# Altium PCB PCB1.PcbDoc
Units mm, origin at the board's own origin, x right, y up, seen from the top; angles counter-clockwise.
Board outline 99.99 x 40 mm, 2 copper layers (Top Layer, Bottom Layer); 5 components, 6 nets, 38 pads, 0 vias.
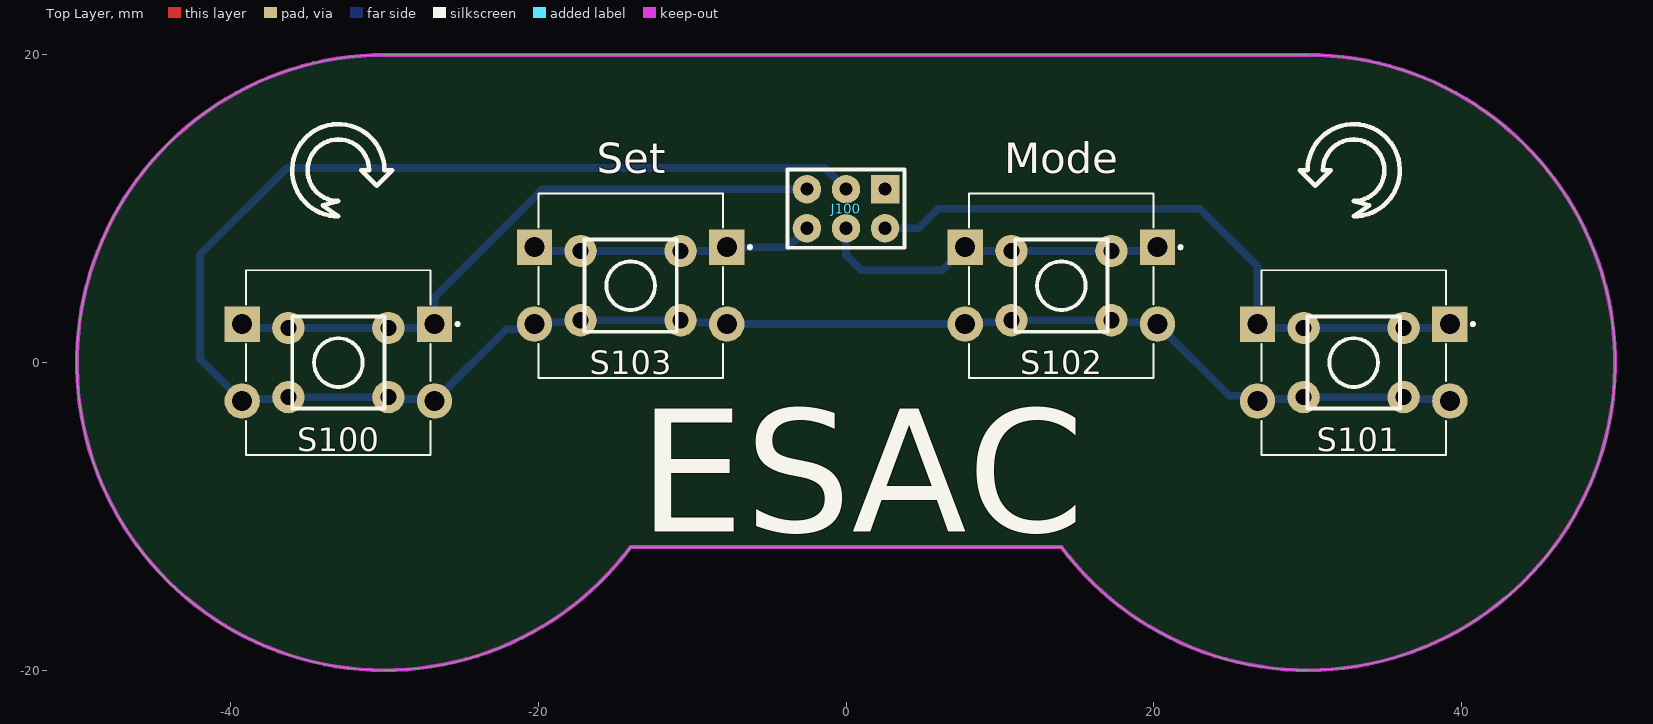
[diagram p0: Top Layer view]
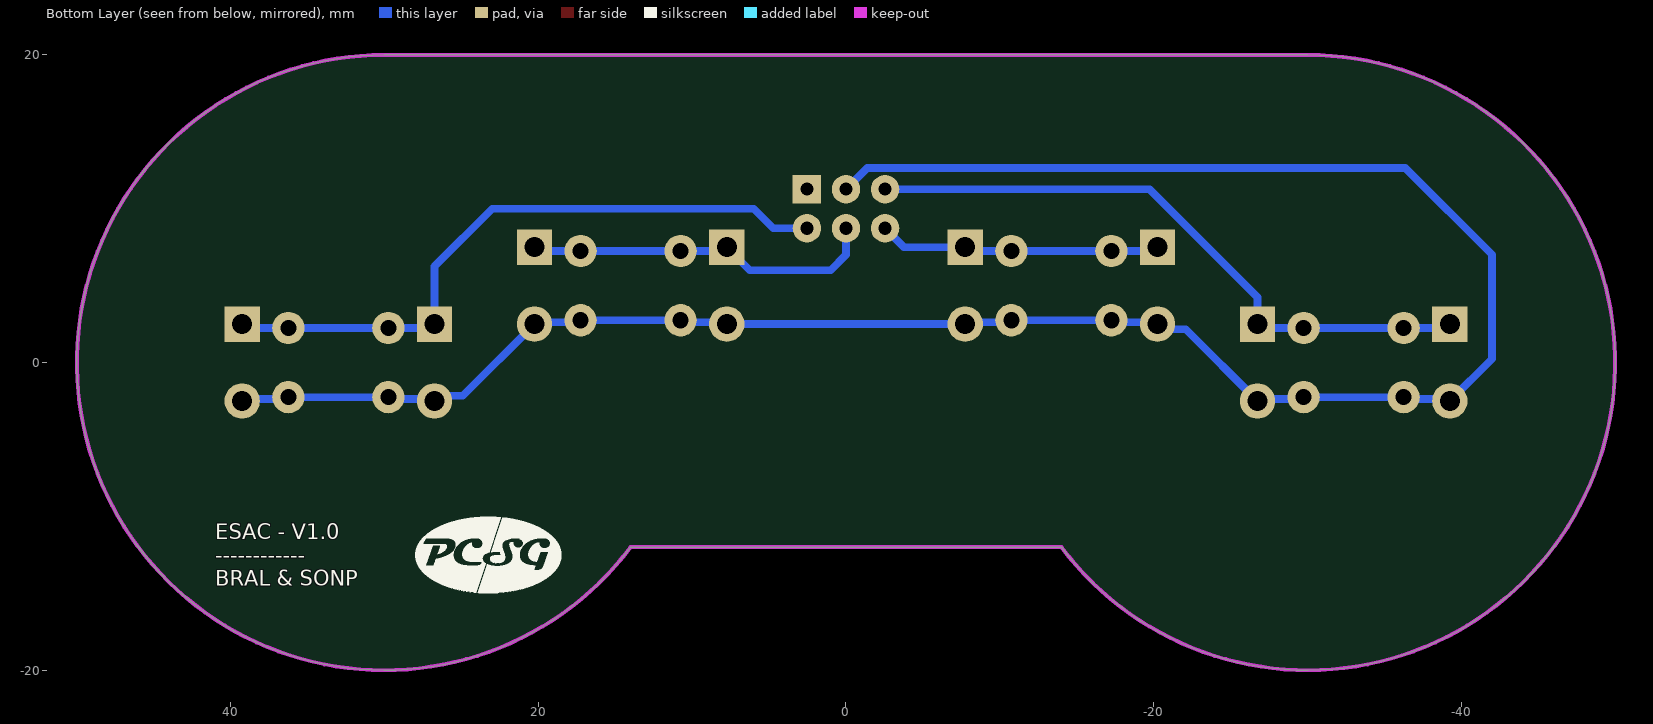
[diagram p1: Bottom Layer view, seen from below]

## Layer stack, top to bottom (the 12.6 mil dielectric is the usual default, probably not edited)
Top Solder: solder mask 0.0102, Solder Resist, Dk 3.5
Top Layer: signal copper 0.0356
Dielectric 1: dielectric 0.32, FR-4, Dk 4.8
Bottom Layer: signal copper 0.0356
Bottom Solder: solder mask 0.0102, Solder Resist, Dk 3.5

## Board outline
-14,-12 cw(c-30,0) -29.999,20 30,20 cw(c30,0) 14,-12

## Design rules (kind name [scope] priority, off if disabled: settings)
Clearance [All] p1: gap=0.5 ignorepadtopadclearanceinfootprint=FALSE except(0.2: Arc-Arc Arc-Track Arc-SMDPad Arc-THPad Arc-Via Arc-Text Arc-Hole Track-Track Track-SMDPad Track-THPad Track-Via Track-Text Track-Hole SMDPad-SMDPad SMDPad-THPad SMDPad-Via SMDPad-Text SMDPad-Hole THPad-THPad THPad-Via THPad-Text THPad-Hole Via-Via Via-Text Via-Hole Text-Text Text-Hole)
HoleSize [All] p1: absolutevalues=TRUE maxlimit=4 minlimit=0.25 maxpercent=80.000 minpercent=20.000
MinimumAnnularRing [All] p1: minimumring=0.3
MinimumSolderMaskSliver [All] p1: minsoldermaskwidth=0
PolygonConnect [All] p1: connectstyle=Relief reliefconductorwidth=0.3 reliefentries=4 polygonreliefangle="90 Angle" airgapwidth=0.3
RoutingVias [All] p1: holewidth=0.6 width=1.2 viastyle="Through Hole" minholewidth=0.5 minwidth=1 maxholewidth=1 maxwidth=2
SilkToSilkClearance [All] p1: silktosilkclearance=0
SilkToSolderMaskClearance [IsPad] p1: minsilkscreentomaskgap=0 clearancetoexposedcopper=TRUE
SolderMaskExpansion [All] p1: expansion=0.102 istentingtop=FALSE
Width [All] p1: maxlimit=6 minlimit=0.2 preferedwidth=0.5
26 further rules are at their usual default settings.

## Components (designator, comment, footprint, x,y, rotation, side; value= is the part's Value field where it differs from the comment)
J100 "CON 2x3" J_2x3 0,10 r180 top
S100 "Taster4Kl." S_THT_TasterKomb. -33,0 r180 top
S101 "Taster4Kl." S_THT_TasterKomb. 33,0 r180 top
S102 "Taster4Kl." S_THT_TasterKomb. 14,5 r180 top
S103 "Taster4Kl." S_THT_TasterKomb. -14,5 r180 top

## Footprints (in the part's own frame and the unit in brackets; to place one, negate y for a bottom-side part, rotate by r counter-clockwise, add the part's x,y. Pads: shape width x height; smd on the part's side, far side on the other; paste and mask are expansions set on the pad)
J_2x3 [mm] "LB-2024-04-19"
  rect 1.85x1.85 hole 0.85 mask+0.102: 1(-2.54,-1.27)
  round 1.85 hole 0.85 mask+0.102: 2(-2.54,1.27) 3(0,-1.27) 4(0,1.27) 5(2.54,-1.27) 6(2.54,1.27)
  silkscreen extent -3.81,-2.54 3.81,2.54
S_THT_TasterKomb. [mm] "LB-2024-04-17"
  rect 2.3x2.3 hole 1.3: 1(-6.25,-2.5) 1(6.25,-2.5)
  round 2.1 hole 1.05: 1(-3.25,-2.25) 1(3.25,-2.25) 2(-3.25,2.25) 2(3.25,2.25)
  round 2.3 hole 1.3: 2(-6.25,2.5) 2(6.25,2.5)
  silkscreen extent -7.85,-6 6,6

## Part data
J100: library part "J_THT_IDC 2x3", "Stecker"
S100 S101 S102 S103: library part S_THT_Taster, "Taster"

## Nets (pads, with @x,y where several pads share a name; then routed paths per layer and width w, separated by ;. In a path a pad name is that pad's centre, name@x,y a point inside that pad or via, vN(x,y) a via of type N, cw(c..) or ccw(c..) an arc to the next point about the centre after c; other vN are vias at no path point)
+5V: J100.3 S100.2 S101.2 S102.2 S103.2 | length 139.4
  Top Layer w0.5: J100.3@-0.258,11.528 J100.3
  Bottom Layer w0.5: J100.3 -1.375,12.645 -36.355,12.645 -42,7 -42,0.25 -39.25,-2.5 -39.125,-2.375 -36.375,-2.375 -36.25,-2.25 -29.75,-2.25 -29.625,-2.375 -26.875,-2.375 -26.75,-2.5 -22.094,2.156 -20.594,2.156 -20.25,2.5 -20.125,2.625 -17.375,2.625 -17.25,2.75 -10.75,2.75 -10.625,2.625 -7.875,2.625 -7.75,2.5 7.75,2.5 7.875,2.625 10.625,2.625 10.75,2.75 17.25,2.75 17.375,2.625 20.125,2.625 20.25,2.5 24.906,-2.156 26.406,-2.156 26.75,-2.5 26.875,-2.375 29.625,-2.375 29.75,-2.25 36.25,-2.25 36.375,-2.375 39.125,-2.375 S101.2@39.25,-2.5
GND: J100.1
T-180: J100.4 S102.1 | length 23.2
  Bottom Layer w0.5: J100.4 0,7 1,6 6.25,6 7.75,7.5 8,7.25 10.75,7.25 17.25,7.25 20,7.25 S102.1@20.25,7.5
T-+: J100.5 S100.1 | length 41.6
  Bottom Layer w0.5: S100.1@-39.25,2.5 -39,2.25 -36.25,2.25 -29.75,2.25 -27,2.25 -26.75,2.5 -26.75,4.25 -19.73,11.27 J100.5
T--: J100.2 S101.1 | length 42.7
  Bottom Layer w0.5: J100.2 4.73,8.73 6,10 23,10 26.75,6.25 26.75,2.5 27,2.25 29.75,2.25 36.25,2.25 39,2.25 S101.1@39.25,2.5
T-Play: J100.6 S103.1 | length 18.4
  Bottom Layer w0.5: S103.1@-20.25,7.5 -20,7.25 -17.25,7.25 -10.75,7.25 -8,7.25 -7.75,7.5 -3.77,7.5 J100.6

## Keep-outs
Keep-Out Layer:
  the board outline again, w0.254

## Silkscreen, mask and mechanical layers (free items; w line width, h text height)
Top Overlay:
  lines w0.3: -34.018,10.216 -33,9.5 cw(c-33,12.5) -30,12.5 -29.5,12.5 -30.5,11.5 -31.5,12.5 -31,12.5 ccw(c-33,12.5) -33,10.5 -34.018,10.216 ; 29.5,12.5 30.5,11.5 31.5,12.5 31,12.5 cw(c33,12.5) 33,10.5 34.018,10.216 33,9.5 ccw(c33,12.5) 30,12.5 29.5,12.5
  text "Set" at -16.2,12.3 h2
  text "Mode" at 10.3,12.3 h2
  text "ESAC" at -13.5,-11 h8
Bottom Overlay:
  drawing of 2 lines, arcs and shapes, not listed
  text "ESAC - V1.0 / ------------ / BRAL & SONP" at 41,-14.5 h1
Mechanical 2:
  circle w0.1: c30,0 r1
  circle w0.1: c-30,0 r1
  circle w0.1: c0,0 r1
  circle w0.05: c-14,5 r0.025
  lines w0.1: -29.999,20 -30.002,20 ccw(c-30,0) -14.262,-12.342 ; -39,-6 -39,6 -27,6 -27,-6 -39,-6 ; -20,-1 -20,11 -8,11 -8,-1 -20,-1 ; 8,-1 20,-1 20,11 8,11 8,-1 ; 27,-6 39,-6 39,6 27,6 27,-6
Kontur:
  lines w0.1: -29.999,20 ccw(c-30,0) -14,-12 0,-12 14,-12 ccw(c30,0) 30,20 -29.999,20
